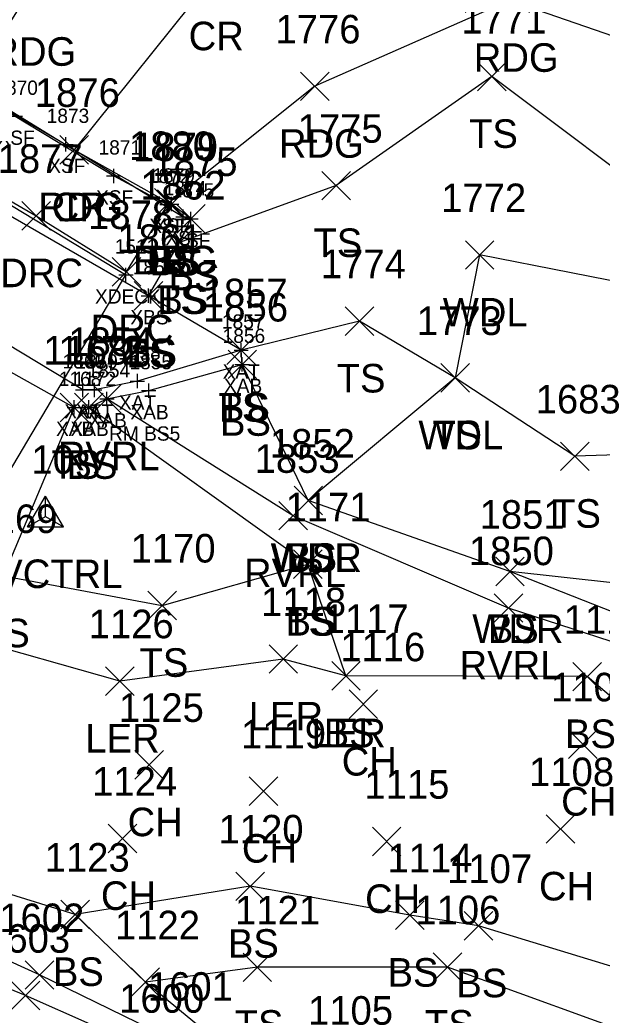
# Model space of a CAD drawing. Extents: x 1600281 to 1602254, y 862855 to 863227.
# Drawn here: x 1602065.8 to 1602106.5, y 863032.2 to 863101.9 of the extents above; entities that cross this region are included whole.
import ezdxf

# ---------------------------------------------------------------- set-up
doc = ezdxf.new("R2010")
doc.units = 0
for name, color, linetype in [('B_A', 7, 'Continuous'), ('B_C', 7, 'Continuous'), ('B_I', 7, 'Continuous'), ('B_TIC', 7, 'Continuous'), ('BDEFAULT', 7, 'Continuous'), ('BELB', 7, 'Continuous'), ('BSE', 7, 'Continuous'), ('BSUBM', 7, 'Continuous'), ('C_A', 7, 'Continuous'), ('C_I', 7, 'Continuous'), ('CPSM', 7, 'Continuous'), ('L_A', 7, 'Continuous'), ('L_I', 7, 'Continuous'), ('L_TIC', 7, 'Continuous'), ('LARO', 7, 'Continuous'), ('LAWA', 7, 'Continuous'), ('LAWE', 7, 'Continuous'), ('LELB', 7, 'Continuous'), ('P_A', 7, 'Continuous'), ('P_I', 7, 'Continuous'), ('P_TIC', 7, 'Continuous'), ('PEU', 7, 'Continuous'), ('PRC', 7, 'Continuous'), ('R_A', 7, 'Continuous'), ('R_I', 7, 'Continuous'), ('R_TIC', 7, 'Continuous'), ('RDP', 7, 'Continuous')]:
    doc.layers.add(name, color=color, linetype=linetype)

msp = doc.modelspace()

# ---------------------------------------------------------------- linework, layer by layer
at = {"layer": 'B_TIC'}
for p, q in [((1602068.993, 863093.14), (1602069.068, 863093.14)), ((1602072.341, 863090.927), (1602072.416, 863090.927)), ((1602076.075, 863088.93), (1602076.15, 863088.93)), ((1602076.393, 863088.962), (1602076.468, 863088.962)), ((1602077.187, 863088.071), (1602077.263, 863088.071)), ((1602077.745, 863087.924), (1602077.82, 863087.924)), ((1602073.188, 863083.996), (1602073.264, 863083.996)), ((1602073.188, 863083.996), (1602073.264, 863083.996)), ((1602074.763, 863082.541), (1602074.839, 863082.541)), ((1602081.259, 863078.736), (1602081.334, 863078.736)), ((1602081.336, 863077.74), (1602081.412, 863077.74)), ((1602073.995, 863076.571), (1602074.071, 863076.571)), ((1602070.173, 863075.952), (1602070.248, 863075.952)), ((1602071.001, 863075.947), (1602071.076, 863075.947)), ((1602074.787, 863075.9), (1602074.862, 863075.9)), ((1602071.858, 863075.326), (1602071.933, 863075.326)), ((1602069.58, 863074.729), (1602069.655, 863074.729)), ((1602070.594, 863074.727), (1602070.67, 863074.727))]:
    msp.add_line(p, q, dxfattribs=at)
for points in [[(1602064.942, 863095.106), (1602065.942, 863095.106)], [(1602068.989, 863092.64), (1602068.989, 863093.64)], [(1602068.489, 863093.14), (1602069.489, 863093.14)], [(1602072.337, 863090.427), (1602072.337, 863091.427)], [(1602071.837, 863090.927), (1602072.837, 863090.927)], [(1602076.071, 863088.43), (1602076.071, 863089.43)], [(1602076.389, 863088.462), (1602076.389, 863089.462)], [(1602075.571, 863088.93), (1602076.571, 863088.93)], [(1602075.889, 863088.962), (1602076.889, 863088.962)], [(1602077.184, 863087.571), (1602077.184, 863088.571)], [(1602077.741, 863087.424), (1602077.741, 863088.424)], [(1602076.684, 863088.071), (1602077.684, 863088.071)], [(1602077.241, 863087.924), (1602078.241, 863087.924)], [(1602073.185, 863083.496), (1602073.185, 863084.496)], [(1602073.185, 863083.496), (1602073.185, 863084.496)], [(1602072.685, 863083.996), (1602073.685, 863083.996)], [(1602072.685, 863083.996), (1602073.685, 863083.996)], [(1602074.76, 863082.041), (1602074.76, 863083.041)], [(1602074.26, 863082.541), (1602075.26, 863082.541)], [(1602080.755, 863078.736), (1602081.755, 863078.736)], [(1602081.255, 863078.236), (1602081.255, 863079.236)], [(1602081.333, 863077.24), (1602081.333, 863078.24)], [(1602080.833, 863077.74), (1602081.833, 863077.74)], [(1602073.492, 863076.571), (1602074.492, 863076.571)], [(1602073.992, 863076.071), (1602073.992, 863077.071)], [(1602069.669, 863075.952), (1602070.669, 863075.952)], [(1602070.169, 863075.452), (1602070.169, 863076.452)], [(1602070.497, 863075.947), (1602071.497, 863075.947)], [(1602070.997, 863075.447), (1602070.997, 863076.447)], [(1602074.283, 863075.9), (1602075.283, 863075.9)], [(1602074.783, 863075.4), (1602074.783, 863076.4)], [(1602069.576, 863074.229), (1602069.576, 863075.229)], [(1602070.591, 863074.227), (1602070.591, 863075.227)], [(1602071.354, 863075.326), (1602072.354, 863075.326)], [(1602071.854, 863074.826), (1602071.854, 863075.826)], [(1602069.076, 863074.729), (1602070.076, 863074.729)], [(1602070.091, 863074.727), (1602071.091, 863074.727)]]:
    msp.add_lwpolyline(points, dxfattribs=at)
at = {"layer": 'BDEFAULT'}
for points in [[(1602060.799, 863098.174), (1602060.789, 863097.925), (1602068.989, 863093.14), (1602077.184, 863088.071), (1602077.741, 863087.924)], [(1602062.056, 863097.058), (1602062.243, 863097.151), (1602065.442, 863095.106), (1602072.337, 863090.927), (1602076.071, 863088.93), (1602076.389, 863088.962)]]:
    msp.add_lwpolyline(points, dxfattribs=at)
at = {"layer": 'BELB'}
for points in [[(1602048.292, 863041.97), (1602034.377, 863049.991), (1602059.57, 863092.252), (1602073.185, 863083.996)], [(1602048.292, 863041.97), (1602073.185, 863083.996)]]:
    msp.add_lwpolyline(points, dxfattribs=at)
at = {"layer": 'BSE'}
msp.add_lwpolyline([(1602074.76, 863082.541), (1602057.575, 863092.444)], dxfattribs=at)
at = {"layer": 'BSUBM'}
for points in [[(1602081.255, 863078.736), (1602073.992, 863076.571), (1602070.997, 863075.947), (1602070.169, 863075.952), (1602054.178, 863085.612)], [(1602053.028, 863084.403), (1602060.693, 863079.286), (1602061.798, 863079.055), (1602069.576, 863074.729), (1602070.591, 863074.727), (1602071.854, 863075.326), (1602074.783, 863075.9), (1602081.333, 863077.74)]]:
    msp.add_lwpolyline(points, dxfattribs=at)
at = {"layer": 'CPSM'}
for p, q in [((1602066.308, 863066.36), (1602067.558, 863068.525)), ((1602068.808, 863066.36), (1602067.558, 863068.525)), ((1602067.558, 863067.081), (1602067.558, 863068.525)), ((1602066.308, 863066.36), (1602067.558, 863067.081)), ((1602067.558, 863067.081), (1602067.558, 863067.081)), ((1602067.558, 863067.081), (1602068.808, 863066.36)), ((1602066.308, 863066.36), (1602068.808, 863066.36))]:
    msp.add_line(p, q, dxfattribs=at)
at = {"layer": 'L_TIC'}
for points in [[(1602097.793, 863096.894), (1602099.793, 863098.894)], [(1602099.793, 863096.894), (1602097.793, 863098.894)], [(1602086.901, 863089.252), (1602088.901, 863091.252)], [(1602088.901, 863089.252), (1602086.901, 863091.252)], [(1602075.187, 863088.042), (1602077.187, 863090.042)], [(1602077.187, 863088.042), (1602075.187, 863090.042)], [(1602075.389, 863087.962), (1602077.389, 863089.962)], [(1602077.389, 863087.962), (1602075.389, 863089.962)], [(1602076.741, 863086.924), (1602078.741, 863088.924)], [(1602078.741, 863086.924), (1602076.741, 863088.924)], [(1602075.946, 863085.276), (1602077.946, 863087.276)], [(1602077.946, 863085.276), (1602075.946, 863087.276)], [(1602075.946, 863085.276), (1602077.946, 863087.276)], [(1602077.946, 863085.276), (1602075.946, 863087.276)], [(1602096.946, 863084.396), (1602098.946, 863086.396)], [(1602098.946, 863084.396), (1602096.946, 863086.396)], [(1602073.76, 863081.541), (1602075.76, 863083.541)], [(1602075.76, 863081.541), (1602073.76, 863083.541)], [(1602073.76, 863081.541), (1602075.76, 863083.541)], [(1602075.76, 863081.541), (1602073.76, 863083.541)], [(1602088.529, 863079.772), (1602090.529, 863081.772)], [(1602090.529, 863079.772), (1602088.529, 863081.772)], [(1602080.255, 863077.736), (1602082.255, 863079.736)], [(1602082.255, 863077.736), (1602080.255, 863079.736)], [(1602080.255, 863077.736), (1602082.255, 863079.736)], [(1602082.255, 863077.736), (1602080.255, 863079.736)], [(1602080.333, 863076.74), (1602082.333, 863078.74)], [(1602082.333, 863076.74), (1602080.333, 863078.74)], [(1602095.24, 863075.794), (1602097.24, 863077.794)], [(1602097.24, 863075.794), (1602095.24, 863077.794)], [(1602095.24, 863075.794), (1602097.24, 863077.794)], [(1602097.24, 863075.794), (1602095.24, 863077.794)], [(1602070.854, 863074.326), (1602072.854, 863076.326)], [(1602072.854, 863074.326), (1602070.854, 863076.326)], [(1602068.576, 863073.729), (1602070.576, 863075.729)], [(1602070.576, 863073.729), (1602068.576, 863075.729)], [(1602069.591, 863073.727), (1602071.591, 863075.727)], [(1602071.591, 863073.727), (1602069.591, 863075.727)], [(1602103.607, 863070.304), (1602105.607, 863072.304)], [(1602105.607, 863070.304), (1602103.607, 863072.304)], [(1602084.955, 863067.217), (1602086.955, 863069.217)], [(1602086.955, 863067.217), (1602084.955, 863069.217)], [(1602084.955, 863067.217), (1602086.955, 863069.217)], [(1602086.955, 863067.217), (1602084.955, 863069.217)], [(1602084.955, 863067.217), (1602086.955, 863069.217)], [(1602086.955, 863067.217), (1602084.955, 863069.217)], [(1602083.888, 863066.147), (1602085.888, 863068.147)], [(1602085.888, 863066.147), (1602083.888, 863068.147)], [(1602084.918, 863062.754), (1602086.918, 863064.754)], [(1602086.918, 863062.754), (1602084.918, 863064.754)], [(1602084.918, 863062.754), (1602086.918, 863064.754)], [(1602086.918, 863062.754), (1602084.918, 863064.754)], [(1602099.07, 863062.236), (1602101.07, 863064.236)], [(1602101.07, 863062.236), (1602099.07, 863064.236)], [(1602099.07, 863062.236), (1602101.07, 863064.236)], [(1602101.07, 863062.236), (1602099.07, 863064.236)], [(1602074.728, 863059.869), (1602076.728, 863061.869)], [(1602076.728, 863059.869), (1602074.728, 863061.869)], [(1602098.972, 863059.685), (1602100.972, 863061.685)], [(1602100.972, 863059.685), (1602098.972, 863061.685)], [(1602083.205, 863056.115), (1602085.205, 863058.115)], [(1602085.205, 863056.115), (1602083.205, 863058.115)], [(1602071.763, 863054.569), (1602073.763, 863056.569)], [(1602073.763, 863054.569), (1602071.763, 863056.569)], [(1602087.591, 863054.936), (1602089.591, 863056.936)], [(1602089.591, 863054.936), (1602087.591, 863056.936)], [(1602087.591, 863054.936), (1602089.591, 863056.936)], [(1602089.591, 863054.936), (1602087.591, 863056.936)], [(1602104.477, 863054.883), (1602106.477, 863056.883)], [(1602106.477, 863054.883), (1602104.477, 863056.883)], [(1602088.805, 863052.958), (1602090.805, 863054.958)], [(1602090.805, 863052.958), (1602088.805, 863054.958)], [(1602104.162, 863050.152), (1602106.162, 863052.152)], [(1602106.162, 863050.152), (1602104.162, 863052.152)], [(1602073.818, 863048.713), (1602075.818, 863050.713)], [(1602075.818, 863048.713), (1602073.818, 863050.713)], [(1602081.813, 863046.862), (1602083.813, 863048.862)], [(1602083.813, 863046.862), (1602081.813, 863048.862)], [(1602102.609, 863044.216), (1602104.609, 863046.216)], [(1602104.609, 863044.216), (1602102.609, 863046.216)], [(1602071.949, 863043.552), (1602073.949, 863045.552)], [(1602073.949, 863043.552), (1602071.949, 863045.552)], [(1602090.439, 863043.338), (1602092.439, 863045.338)], [(1602092.439, 863043.338), (1602090.439, 863045.338)], [(1602080.883, 863040.204), (1602082.883, 863042.204)], [(1602082.883, 863040.204), (1602080.883, 863042.204)], [(1602068.632, 863038.23), (1602070.632, 863040.23)], [(1602070.632, 863038.23), (1602068.632, 863040.23)], [(1602068.632, 863038.23), (1602070.632, 863040.23)], [(1602070.632, 863038.23), (1602068.632, 863040.23)], [(1602092.058, 863038.179), (1602094.058, 863040.179)], [(1602094.058, 863038.179), (1602092.058, 863040.179)], [(1602096.872, 863037.437), (1602098.872, 863039.437)], [(1602098.872, 863037.437), (1602096.872, 863039.437)], [(1602081.388, 863034.535), (1602083.388, 863036.535)], [(1602083.388, 863034.535), (1602081.388, 863036.535)], [(1602094.702, 863034.545), (1602096.702, 863036.545)], [(1602096.702, 863034.545), (1602094.702, 863036.545)], [(1602066.142, 863033.999), (1602068.142, 863035.999)], [(1602068.142, 863033.999), (1602066.142, 863035.999)], [(1602073.55, 863033.496), (1602075.55, 863035.496)], [(1602075.55, 863033.496), (1602073.55, 863035.496)], [(1602073.55, 863033.496), (1602075.55, 863035.496)], [(1602075.55, 863033.496), (1602073.55, 863035.496)], [(1602065.153, 863032.557), (1602067.153, 863034.557)], [(1602067.153, 863032.557), (1602065.153, 863034.557)]]:
    msp.add_lwpolyline(points, dxfattribs=at)
at = {"layer": 'LARO'}
msp.add_lwpolyline([(1602088.591, 863055.936), (1602084.205, 863057.115), (1602072.763, 863055.569), (1602061.695, 863058.699), (1602046.297, 863060.847), (1602041.29, 863063.794), (1602038.414, 863067.763), (1602029.525, 863077.549), (1602024.193, 863078.94), (1602013.468, 863079.959), (1602006.072, 863081.659), (1601997.978, 863081.824), (1601978.825, 863086.781)], dxfattribs=at)
at = {"layer": 'LAWA'}
for points in [[(1602234.913, 863039.661), (1602192.354, 863044.306), (1602167.073, 863054.435), (1602131.757, 863070.495), (1602122.445, 863071.865), (1602110.764, 863082.892), (1602097.946, 863085.396), (1602096.24, 863076.794), (1602085.955, 863068.217)], [(1602181.592, 862874.705), (1602187.9, 862909.632), (1602181.837, 862933.121), (1602183.649, 862946.173), (1602178.29, 862959.028), (1602166.544, 862973.133), (1602158.378, 862984.25), (1602153.067, 863003.854), (1602148.74, 863019.559), (1602142.308, 863032.969), (1602127.676, 863047.243), (1602113.213, 863058.059), (1602100.07, 863063.236), (1602085.955, 863068.217)]]:
    msp.add_lwpolyline(points, dxfattribs=at)
at = {"layer": 'LAWE'}
for points in [[(1602180.629, 862874.479), (1602183.915, 862910.828), (1602179.726, 862932.705), (1602183.058, 862946.011), (1602176.688, 862958.52), (1602164.733, 862972.157), (1602156.512, 862983.111), (1602149.651, 863002.929), (1602145.18, 863017.679), (1602136.969, 863030.892), (1602125.37, 863045.702), (1602111.616, 863056.89), (1602099.972, 863060.685), (1602084.888, 863067.147), (1602071.854, 863075.326)], [(1602098.435, 862879.183), (1602097.38, 862900.93), (1602100.821, 862918.119), (1602111.897, 862945.191), (1602113.655, 862964.279), (1602114.598, 862983.415), (1602109.052, 863000.365), (1602100.599, 863011.379), (1602088.422, 863022.641), (1602086.169, 863023.524), (1602076.977, 863030.193), (1602067.142, 863034.999), (1602054.868, 863040.585)]]:
    msp.add_lwpolyline(points, dxfattribs=at)
at = {"layer": 'LELB'}
for points in [[(1602234.444, 863044.271), (1602194.203, 863054.348), (1602171.396, 863064.066), (1602135.769, 863079.26), (1602125.862, 863083.343), (1602111.986, 863088.002), (1602098.793, 863097.894), (1602087.901, 863090.252), (1602076.946, 863086.276)], [(1602074.76, 863082.541), (1602076.946, 863086.276), (1602077.741, 863087.924), (1602076.389, 863088.962), (1602076.187, 863089.042)], [(1602053.028, 863084.403), (1602044.996, 863082.199), (1602042.897, 863078.832), (1602038.461, 863076.466), (1602036.437, 863071.468), (1602049.302, 863063.059), (1602059.529, 863059.725), (1602064.631, 863062.934), (1602075.728, 863060.869), (1602085.918, 863063.754)], [(1602122.445, 863071.865), (1602104.607, 863071.304), (1602096.24, 863076.794), (1602089.529, 863080.772), (1602081.255, 863078.736), (1602074.76, 863082.541)], [(1602085.955, 863068.217), (1602081.333, 863077.74), (1602081.255, 863078.736)], [(1602069.576, 863074.729), (1602064.631, 863062.934)], [(1602146.601, 862992.785), (1602137.91, 863023.71), (1602135.699, 863030.64), (1602131.78, 863033.528), (1602105.477, 863055.883), (1602088.591, 863055.936), (1602085.918, 863063.754), (1602070.591, 863074.727)], [(1602231.783, 862943.938), (1602226.256, 862961.53), (1602218.486, 862967.018), (1602194.131, 862990.828), (1602188.465, 863004.889), (1602184.539, 863016.137), (1602188.037, 863030.701), (1602174.953, 863034.204), (1602162.968, 863042.411), (1602150.209, 863055.3), (1602142.82, 863056.749), (1602118.66, 863061.185), (1602100.07, 863063.236)], [(1602099.842, 862878.347), (1602100.95, 862904.784), (1602110.589, 862929.642), (1602115.654, 862954.701), (1602118.276, 862973.935), (1602116.239, 862983.386), (1602108.039, 863004.489), (1602102.906, 863010.993), (1602095.897, 863019.119), (1602089.354, 863024.498), (1602085.541, 863025.448), (1602074.55, 863034.496), (1602069.632, 863039.23), (1602052.338, 863044.601)], [(1602116.925, 863005.507), (1602119.588, 863020.247), (1602116.459, 863032.769), (1602097.872, 863038.437), (1602093.058, 863039.179), (1602081.883, 863041.204), (1602069.632, 863039.23)], [(1602075.62, 863029.355), (1602066.153, 863033.557), (1602055.206, 863038.057)], [(1602116.925, 863005.507), (1602113.863, 863021.47), (1602110.735, 863030.077), (1602095.702, 863035.545), (1602082.388, 863035.535), (1602074.55, 863034.496)]]:
    msp.add_lwpolyline(points, dxfattribs=at)
at = {"layer": 'P_TIC'}
for points in [[(1602085.406, 863096.204), (1602087.406, 863098.204)], [(1602087.406, 863096.204), (1602085.406, 863098.204)], [(1602068.562, 863091.761), (1602070.562, 863093.761)], [(1602070.562, 863091.761), (1602068.562, 863093.761)], [(1602068.562, 863091.761), (1602070.562, 863093.761)], [(1602070.562, 863091.761), (1602068.562, 863093.761)], [(1602075.187, 863088.042), (1602077.187, 863090.042)], [(1602077.187, 863088.042), (1602075.187, 863090.042)], [(1602075.187, 863088.042), (1602077.187, 863090.042)], [(1602077.187, 863088.042), (1602075.187, 863090.042)]]:
    msp.add_lwpolyline(points, dxfattribs=at)
at = {"layer": 'PEU'}
for points in [[(1602239.323, 863063.193), (1602201.856, 863077.578), (1602181.734, 863084.138), (1602148.756, 863103.129), (1602126.101, 863112.297), (1602096.314, 863123.237), (1602085.65, 863117.237), (1602075.424, 863112.315), (1602066.282, 863103.641), (1602062.254, 863097.245), (1602069.562, 863092.761), (1602076.187, 863089.042)], [(1602235.306, 863048.086), (1602195.245, 863059.48), (1602172.509, 863066.536), (1602139.216, 863086.847), (1602117.278, 863097.261), (1602100.046, 863103.218), (1602086.406, 863097.204), (1602076.187, 863089.042)]]:
    msp.add_lwpolyline(points, dxfattribs=at)
at = {"layer": 'PRC'}
msp.add_lwpolyline([(1602236.396, 863054.637), (1602198.655, 863067.234), (1602177.306, 863075.301), (1602143.813, 863093.879), (1602121.553, 863104.551), (1602098.781, 863113.504), (1602079.146, 863104.728), (1602069.562, 863092.761)], dxfattribs=at)
at = {"layer": 'R_TIC'}
for points in [[(1602075.187, 863088.042), (1602077.187, 863090.042)], [(1602077.187, 863088.042), (1602075.187, 863090.042)], [(1602065.905, 863087.144), (1602067.905, 863089.144)], [(1602067.905, 863087.144), (1602065.905, 863089.144)], [(1602072.232, 863083.216), (1602074.232, 863085.216)], [(1602074.232, 863083.216), (1602072.232, 863085.216)]]:
    msp.add_lwpolyline(points, dxfattribs=at)
at = {"layer": 'RDP'}
msp.add_lwpolyline([(1602062.254, 863097.245), (1602059.623, 863092.367), (1602066.905, 863088.144), (1602073.232, 863084.216), (1602076.187, 863089.042)], dxfattribs=at)

# ---------------------------------------------------------------- texts
at = {"layer": 'B_A'}
for s, p in [('XSF', (1602064.202, 863093.106)), ('XSF', (1602067.749, 863091.14)), ('XSF', (1602071.097, 863088.927)), ('XSF', (1602074.831, 863086.93)), ('XSF', (1602075.149, 863086.962)), ('XSF', (1602075.943, 863086.071)), ('XSF', (1602076.501, 863085.924)), ('XDECK', (1602071.027, 863081.996)), ('XDECK', (1602071.027, 863081.996)), ('XBS', (1602073.5, 863080.541)), ('XAT', (1602079.96, 863076.736)), ('XAB', (1602080.053, 863075.74)), ('XAT', (1602072.697, 863074.571)), ('XAT', (1602068.874, 863073.952)), ('XAT', (1602069.702, 863073.947)), ('XAB', (1602073.504, 863073.9)), ('XAB', (1602070.575, 863073.326)), ('XAB', (1602068.297, 863072.729)), ('XAB', (1602069.311, 863072.727))]:
    msp.add_text(s, height=1, dxfattribs=at).set_placement(p)
at = {"layer": 'B_C'}
msp.add_text('RM BS5', height=1, dxfattribs=at).set_placement((1602072.012, 863072.4))
at = {"layer": 'B_I'}
for s, p in [('1870', (1602064.052, 863096.606)), ('1873', (1602067.643, 863094.64)), ('1871', (1602071.274, 863092.427)), ('1872', (1602074.725, 863090.43)), ('1879', (1602075.039, 863090.462)), ('1874', (1602075.837, 863089.571)), ('1875', (1602076.395, 863089.424)), ('1511', (1602072.405, 863085.496)), ('1511', (1602072.405, 863085.496)), ('1861', (1602073.673, 863084.041)), ('1857', (1602079.909, 863080.236)), ('1856', (1602079.959, 863079.24)), ('1858', (1602072.645, 863078.071)), ('1860', (1602068.756, 863077.452)), ('1859', (1602069.647, 863077.447)), ('1855', (1602073.437, 863077.4)), ('1854', (1602070.508, 863076.826)), ('1168', (1602068.49, 863076.229)), ('1172', (1602069.528, 863076.227))]:
    msp.add_text(s, height=1, dxfattribs=at).set_placement(p)
at = {"layer": 'C_A'}
msp.add_text('HVCTRL', height=2, dxfattribs=at).set_placement((1602062.251, 863062.081))
at = {"layer": 'C_I'}
msp.add_text('10', height=2, dxfattribs=at).set_placement((1602066.574, 863070.081))
at = {"layer": 'L_A'}
for s, p in [('TS', (1602097.203, 863092.894)), ('TS', (1602086.311, 863085.252)), ('BS', (1602074.628, 863084.042)), ('BS', (1602074.83, 863083.962)), ('BS', (1602076.182, 863082.924)), ('TS', (1602075.355, 863081.276)), ('BS', (1602075.387, 863081.276)), ('WDL', (1602095.363, 863080.396)), ('TS', (1602073.169, 863077.541)), ('BS', (1602073.201, 863077.541)), ('TS', (1602087.939, 863075.772)), ('TS', (1602079.665, 863073.736)), ('BS', (1602079.696, 863073.736)), ('BS', (1602079.774, 863072.74)), ('WDL', (1602093.658, 863071.794)), ('TS', (1602094.65, 863071.794)), ('TS', (1602067.986, 863069.729)), ('RVRL', (1602068.421, 863070.326)), ('BS', (1602069.031, 863069.727)), ('TS', (1602103.017, 863066.304)), ('WDR', (1602083.317, 863063.217)), ('WDL', (1602083.372, 863063.217)), ('BS', (1602084.396, 863063.217)), ('RVRL', (1602081.455, 863062.147)), ('TS', (1602084.327, 863058.754)), ('BS', (1602084.359, 863058.754)), ('TS', (1602063.041, 863057.934)), ('TS', (1602063.041, 863057.934)), ('WDR', (1602097.432, 863058.236)), ('BS', (1602098.511, 863058.236)), ('TS', (1602074.138, 863055.869)), ('RVRL', (1602096.539, 863055.685)), ('LER', (1602081.787, 863052.115)), ('LER', (1602086.174, 863050.936)), ('BS', (1602087.032, 863050.936)), ('BS', (1602103.918, 863050.883)), ('LER', (1602070.345, 863050.569)), ('CH', (1602088.293, 863048.958)), ('CH', (1602103.65, 863046.152)), ('CH', (1602073.306, 863044.713)), ('CH', (1602081.302, 863042.862)), ('CH', (1602102.098, 863040.216)), ('CH', (1602071.437, 863039.552)), ('CH', (1602089.927, 863039.338)), ('BS', (1602080.324, 863036.204)), ('BS', (1602068.073, 863034.23)), ('BS', (1602068.073, 863034.23)), ('BS', (1602091.499, 863034.179)), ('BS', (1602096.313, 863033.437)), ('TS', (1602080.798, 863030.535)), ('TS', (1602094.112, 863030.545))]:
    msp.add_text(s, height=2, dxfattribs=at).set_placement(p)
at = {"layer": 'L_I'}
for s, p in [('1771', (1602096.667, 863100.894)), ('1775', (1602085.208, 863093.252)), ('1880', (1602073.407, 863092.042)), ('1879', (1602073.689, 863091.962)), ('1875', (1602075.048, 863090.924)), ('1862', (1602074.206, 863089.276)), ('1862', (1602074.206, 863089.276)), ('1772', (1602095.253, 863088.396)), ('1861', (1602072.586, 863085.541)), ('1861', (1602072.586, 863085.541)), ('1774', (1602086.836, 863083.772)), ('1857', (1602078.562, 863081.736)), ('1857', (1602078.562, 863081.736)), ('1856', (1602078.585, 863080.74)), ('1773', (1602093.548, 863079.794)), ('1773', (1602093.548, 863079.794)), ('1854', (1602069.161, 863078.326)), ('1168', (1602067.403, 863077.729)), ('1172', (1602068.465, 863077.727)), ('1683', (1602101.867, 863074.304)), ('1852', (1602083.262, 863071.217)), ('1852', (1602083.262, 863071.217)), ('1852', (1602083.262, 863071.217)), ('1853', (1602082.195, 863070.147)), ('1171', (1602084.359, 863066.754)), ('1171', (1602084.359, 863066.754)), ('1851', (1602097.944, 863066.236)), ('1851', (1602097.944, 863066.236)), ('1169', (1602062.45, 863065.934)), ('1169', (1602062.45, 863065.934)), ('1170', (1602073.516, 863063.869)), ('1850', (1602097.192, 863063.685)), ('1118', (1602082.646, 863060.115)), ('1126', (1602070.582, 863058.569)), ('1117', (1602087.032, 863058.936)), ('1117', (1602087.032, 863058.936)), ('1110', (1602103.831, 863058.883)), ('1116', (1602088.191, 863056.958)), ('1109', (1602102.949, 863054.152)), ('1125', (1602072.692, 863052.713)), ('1119', (1602081.246, 863050.862)), ('1108', (1602101.405, 863048.216)), ('1124', (1602070.823, 863047.552)), ('1115', (1602089.88, 863047.338)), ('1120', (1602079.67, 863044.204)), ('1123', (1602067.506, 863042.23)), ('1123', (1602067.506, 863042.23)), ('1114', (1602091.499, 863042.179)), ('1107', (1602095.667, 863041.437)), ('1121', (1602080.829, 863038.535)), ('1106', (1602093.443, 863038.545)), ('1602', (1602064.323, 863037.999)), ('1122', (1602072.424, 863037.496)), ('1122', (1602072.424, 863037.496)), ('1603', (1602063.334, 863036.557)), ('1601', (1602074.725, 863033.193)), ('1600', (1602072.715, 863032.355)), ('1600', (1602072.715, 863032.355)), ('1105', (1602085.933, 863031.517))]:
    msp.add_text(s, height=2, dxfattribs=at).set_placement(p)
at = {"layer": 'P_A'}
for s, p in [('CR', (1602077.579, 863099.728)), ('RDG', (1602063.771, 863098.641)), ('RDG', (1602097.534, 863098.218)), ('RDG', (1602083.894, 863092.204)), ('RDG', (1602067.051, 863087.761)), ('CR', (1602067.996, 863087.761)), ('RDG', (1602073.675, 863084.042)), ('RDG', (1602073.675, 863084.042))]:
    msp.add_text(s, height=2, dxfattribs=at).set_placement(p)
at = {"layer": 'P_I'}
for s, p in [('1776', (1602083.658, 863100.204)), ('1876', (1602066.814, 863095.761)), ('1876', (1602066.814, 863095.761)), ('1880', (1602073.407, 863092.042)), ('1880', (1602073.407, 863092.042))]:
    msp.add_text(s, height=2, dxfattribs=at).set_placement(p)
at = {"layer": 'R_A'}
for p in [(1602073.675, 863084.042), (1602064.393, 863083.144), (1602070.72, 863079.216)]:
    msp.add_text('DRC', height=2, dxfattribs=at).set_placement(p)
at = {"layer": 'R_I'}
for s, p in [('1880', (1602073.407, 863092.042)), ('1877', (1602064.212, 863091.144)), ('1878', (1602070.539, 863087.216))]:
    msp.add_text(s, height=2, dxfattribs=at).set_placement(p)

doc.saveas('drawing.dxf')
